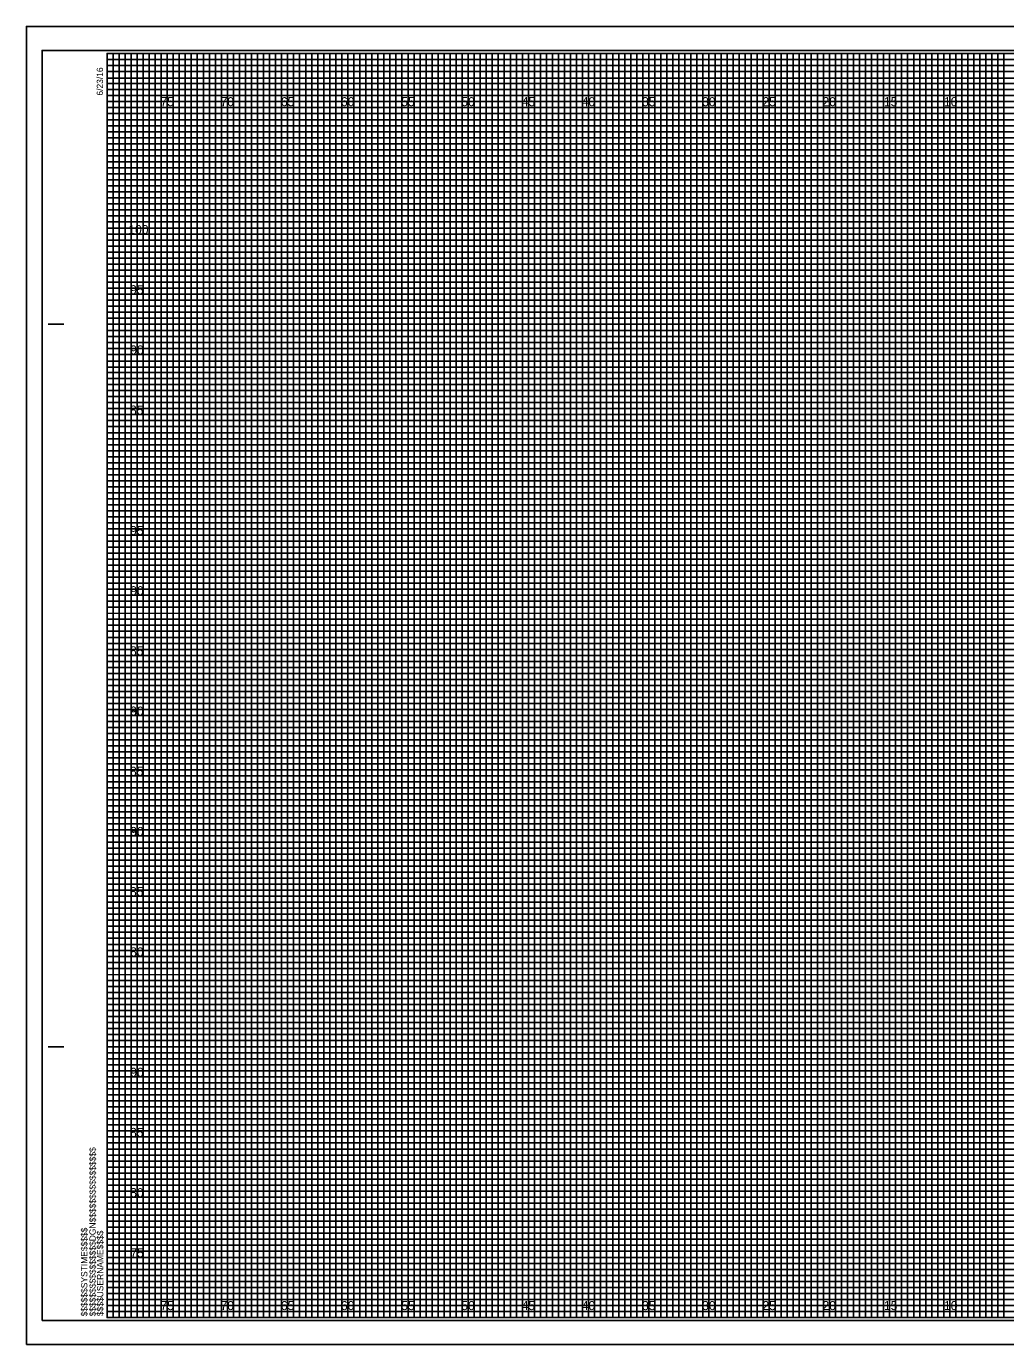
# Model space of a CAD drawing. Extents: x -7 to 182, y -2 to 1647.
# Drawn here: x -6.7 to 74.6, y 217.7 to 327.2 of the extents above; entities that cross this region are included whole.
import ezdxf

# ---------------------------------------------------------------- set-up
doc = ezdxf.new("R2010")
doc.units = 0
for name, color, linetype in [('Exist Cross Section Cell', 7, 'Continuous'), ('Exist XS Ground Line', 7, 'Continuous'), ('Prop CMT Pvmt Course 3', 7, 'Continuous'), ('Prop CMT Pvmt Wedge Surface 1', 7, 'Continuous'), ('Prop CMT Pvmt Wedge Surface 2', 7, 'Continuous'), ('Prop CMT Pvmt Wedge Surface 3', 7, 'Continuous'), ('Prop CMT Shld Paved Course 1', 7, 'Continuous'), ('Prop CMT Shld Paved Course 2', 7, 'Continuous'), ('Prop CMT Shld Paved Course 3', 7, 'Continuous'), ('Prop CMT Slope Grass', 7, 'Continuous'), ('Prop CMT Subgrade Earthwork', 7, 'Continuous')]:
    doc.layers.add(name, color=color, linetype=linetype)

msp = doc.modelspace()

# ---------------------------------------------------------------- linework, layer by layer
at = {"layer": 'Exist XS Ground Line'}
for p, q in [((5, 325), (0, 325)), ((5, 220), (5, 325)), ((15, 325), (10, 325)), ((10, 325), (10, 220)), ((15, 220), (15, 325)), ((25, 325), (20, 325)), ((20, 325), (20, 220)), ((25, 220), (25, 325)), ((35, 325), (30, 325)), ((30, 325), (30, 220)), ((35, 220), (35, 325)), ((45, 325), (40, 325)), ((40, 325), (40, 220)), ((45, 220), (45, 325)), ((55, 325), (50, 325)), ((50, 325), (50, 220)), ((55, 220), (55, 325)), ((65, 325), (60, 325)), ((60, 325), (60, 220)), ((65, 220), (65, 325)), ((75, 325), (70, 325)), ((70, 325), (70, 220)), ((10, 220), (5, 220)), ((20, 220), (15, 220)), ((30, 220), (25, 220)), ((40, 220), (35, 220)), ((50, 220), (45, 220)), ((60, 220), (55, 220)), ((70, 220), (65, 220))]:
    msp.add_line(p, q, dxfattribs=at)
for points in [[(0, 320), (160, 320), (160, 315), (0, 315)], [(0, 310), (160, 310), (160, 305), (0, 305)], [(0, 300), (160, 300), (160, 295), (0, 295)], [(0, 290), (160, 290), (160, 285), (0, 285)], [(0, 280), (160, 280), (160, 275), (0, 275)], [(0, 270), (160, 270), (160, 265), (0, 265)], [(0, 260), (160, 260), (160, 255), (0, 255)], [(0, 250), (160, 250), (160, 245), (0, 245)], [(0, 240), (160, 240), (160, 235), (0, 235)], [(0, 230), (160, 230), (160, 225), (0, 225)]]:
    msp.add_lwpolyline(points, dxfattribs=at)
at = {"layer": 'Prop CMT Pvmt Course 3'}
msp.add_lwpolyline([(-6.7, 217.75), (161.65, 217.75), (161.65, 327.25), (-6.7, 327.25)], close=True, dxfattribs=at)
at = {"layer": 'Prop CMT Pvmt Wedge Surface 1'}
for p, q in [((0, 324.5), (130, 324.5)), ((130, 323.99), (0, 323.99)), ((0, 323.99), (0, 323.5)), ((0, 323.5), (130, 323.5)), ((130, 322.94), (0, 322.94)), ((0, 322.94), (0, 322)), ((0, 322), (160, 322))]:
    msp.add_line(p, q, dxfattribs=at)
for points in [[(0, 321.5), (135, 321.5), (160, 321.5), (160, 321), (0, 321)], [(0, 320.5), (160, 320.5), (160, 319.5), (0, 319.5)], [(0, 319), (160, 319), (160, 318.5), (0, 318.49)], [(0, 318), (160, 318), (160, 317), (0, 317)], [(0, 316.5), (160, 316.5), (160, 316), (0, 316)], [(0, 315.5), (160, 315.5), (160, 314.5), (0, 314.5)], [(0, 314), (160, 314), (160, 313.5), (0, 313.5)], [(0, 313), (160, 313), (160, 312), (0, 312)], [(0, 311.5), (160, 311.5), (160, 311), (0, 311)], [(0, 310.5), (160, 310.5), (160, 309.5), (0, 309.5)], [(0, 309), (160, 309), (160, 308.5), (0, 308.5)], [(0, 308), (160, 308), (160, 306.98), (160, 306.5), (160, 306), (0, 306)], [(0, 307), (160, 307), (160, 306.5), (0, 306.5)], [(0, 305.5), (160, 305.5), (160, 304.5), (0, 304.51)], [(0, 304.51), (160, 304.5), (160, 304), (0, 304)], [(0, 303.5), (160, 303.5), (160, 303), (0, 303)], [(0, 302), (160, 302), (160, 301.5), (0, 301.5)], [(0, 301), (160, 301), (160, 300.5), (0, 300.5)], [(-0.04, 299.44), (160, 299.44), (160, 298.94), (-0.04, 298.94)], [(0, 298.5), (160, 298.5), (160, 298), (0, 298)], [(0, 297), (160, 297), (160, 296.5), (0, 296.5)], [(0, 296), (160, 296), (160, 295.5), (0, 295.5)], [(0, 294.5), (160, 294.5), (160, 294), (0, 294)], [(0, 293.5), (160, 293.5), (160, 293), (0, 293)], [(0, 292), (160, 292), (160, 291.5), (0, 291.5)], [(0, 291), (160, 291), (160, 290.5), (0, 290.5)], [(0, 289.5), (160, 289.5), (160, 288.99), (0, 289)], [(0, 288.5), (160, 288.5), (160, 288), (0, 288)], [(0, 287), (160, 287), (160, 286.5), (0, 286.5)], [(0, 286), (160, 286), (160, 285.5), (0, 285.5)], [(0, 284.5), (160, 284.5), (160, 284), (0, 284)], [(0, 283.5), (160, 283.5), (160, 283), (0, 283)], [(0, 282), (160, 282), (160, 281.5), (0, 281.5)], [(0, 281), (160, 281), (160, 280.5), (0, 280.5)], [(0, 279.5), (160, 279.5), (160, 279), (0, 279)], [(0, 278.5), (160.03, 278.45), (160, 278), (0, 278)], [(0, 277), (160, 277), (160, 276.5), (0, 276.5)], [(0, 276), (160, 276), (160, 275.5), (0, 275.5)], [(0, 274.5), (160, 274.5), (160, 274), (0, 274)], [(0, 273.5), (160, 273.5), (160, 273), (0, 273)], [(0, 272), (160, 272), (160, 271.5), (0, 271.5)], [(0, 271), (160, 271), (160, 270.5), (0, 270.5)], [(0, 269.5), (160, 269.5), (160, 269), (0, 269)], [(0, 268.5), (160, 268.5), (160, 268), (0, 268)], [(0, 267), (160, 267), (160, 266.5), (0, 266.5)], [(0, 266), (160, 266), (160, 265.5), (0, 265.5)], [(0, 264.5), (160, 264.5), (160, 264), (0, 264)], [(0, 263.5), (160, 263.5), (160, 263), (0, 263)], [(0, 262), (160, 262), (160, 261.5), (0, 261.5)], [(0, 261), (160, 261), (160, 260.5), (0, 260.5)], [(0, 259.5), (160, 259.5), (160, 258.99), (0, 259)], [(0, 258.5), (160, 258.5), (160, 258), (0, 258)], [(0, 257), (160, 257), (160, 256.5), (0, 256.5)], [(0, 256), (160, 256), (160, 255.5), (0, 255.5)], [(0, 254.5), (160, 254.5), (160, 254), (0, 254)], [(0, 253.5), (160, 253.5), (160, 253), (0, 253)], [(0, 252), (160, 252), (160, 251.5), (0, 251.5)], [(0, 251), (160, 251), (160, 250.5), (0, 250.5)], [(0, 249.5), (160, 249.5), (160, 249), (0, 249)], [(0, 248.5), (160.03, 248.46), (160, 248), (0, 248)], [(0, 247), (160, 247), (160, 246.5), (0, 246.5)], [(0, 246), (160, 246), (160, 245.5), (0, 245.5)], [(0, 244.5), (160, 244.5), (160, 244), (0, 244)], [(0, 243.5), (160, 243.5), (160, 243), (0, 243)], [(0, 242), (160, 242), (160, 241.5), (0, 241.5)], [(0, 241), (160, 241), (160, 240.5), (0, 240.5)], [(0, 239.5), (160, 239.5), (160, 239), (0, 239)], [(0, 238.5), (160, 238.5), (160, 238), (0, 238)], [(0, 237), (160, 237), (160, 236.5), (0, 236.5)], [(0, 236), (160, 236), (160, 235.5), (0, 235.5)], [(0, 234.5), (160, 234.5), (160, 234), (0, 234)], [(0, 233.5), (160, 233.5), (160, 233), (0, 233)], [(0, 232), (160, 232), (160, 231.5), (0, 231.5)], [(0, 231), (160, 231), (160, 230.5), (0, 230.5)], [(0, 229.5), (160, 229.5), (160, 229), (0, 229)], [(0, 228.5), (160, 228.5), (160, 228), (0, 228)], [(0, 227), (160, 227), (160, 226.5), (0, 226.5)], [(0, 226), (160, 226), (160, 225.5), (0, 225.5)], [(0, 224.5), (160, 224.5), (160, 224), (0, 224)], [(0, 223.5), (160, 223.5), (160, 223), (0, 223)], [(0, 222), (160, 222), (160, 221.5), (0, 221.5)], [(0, 221), (160, 221), (160, 220.5), (0, 220.5)]]:
    msp.add_lwpolyline(points, dxfattribs=at)
at = {"layer": 'Prop CMT Pvmt Wedge Surface 2'}
for p, q in [((-4.9, 302.5), (-3.65, 302.5)), ((-4.85, 302.5), (-3.6, 302.5)), ((-4.9, 242.5), (-3.65, 242.5)), ((-4.85, 242.5), (-3.6, 242.5)), ((0, 220), (0, 220)), ((0, 220), (0, 220)), ((0, 220), (0, 220)), ((0, 220), (0, 220)), ((0, 220), (0, 220)), ((0, 220), (0, 220)), ((0, 220), (0, 220))]:
    msp.add_line(p, q, dxfattribs=at)
msp.add_lwpolyline([(160, 325), (0, 325), (0, 220), (160, 220)], close=True, dxfattribs=at)
at = {"layer": 'Prop CMT Pvmt Wedge Surface 3'}
for points in [[(0, 220), (0.5, 220), (0.5, 325), (1, 325), (1, 220)], [(1, 220), (1.5, 220), (1.5, 325), (2, 325), (2, 220)], [(2.5, 220), (3, 220), (3, 325), (3.5, 325), (3.5, 220)], [(3.5, 220), (4, 220), (4, 325), (4.5, 325), (4.5, 220)], [(5, 220), (5.5, 220), (5.5, 325), (6, 325), (6, 220)], [(6, 220), (6.5, 220), (6.5, 325), (7, 325), (7, 220)], [(7.5, 220), (8, 220), (8, 325), (8.5, 325), (8.5, 220)], [(8.5, 220), (9, 220), (9, 325), (9.5, 325), (9.5, 220)], [(10, 220), (10.5, 220), (10.5, 325), (11, 325), (11, 220)], [(11, 220), (11.5, 220), (11.5, 325), (12, 325), (12, 220)], [(12.5, 220), (13, 220), (13, 325), (13.5, 325), (13.5, 220)], [(13.5, 220), (14, 220), (14, 325), (14.5, 325), (14.5, 220)], [(15, 220), (15.5, 220), (15.5, 325), (16, 325), (16, 220)], [(16, 220), (16.5, 220), (16.5, 325), (17, 325), (17, 220)], [(17.5, 220), (18, 220), (18, 325), (18.5, 325), (18.5, 220)], [(18.5, 220), (19, 220), (19, 325), (19.5, 325), (19.5, 220)], [(20, 220), (20.5, 220), (20.5, 325), (21, 325), (21, 220)], [(21, 220), (21.5, 220), (21.5, 325), (22, 325), (22, 220)], [(22.5, 220), (23, 220), (23, 325), (23.5, 325), (23.5, 220)], [(23.5, 220), (24, 220), (24, 325), (24.5, 325), (24.5, 220)], [(25, 220), (25.5, 220), (25.5, 325), (26, 325), (26, 220)], [(26, 220), (26.5, 220), (26.5, 325), (27, 325), (27, 220)], [(27.5, 220), (28, 220), (28, 325), (28.5, 325), (28.5, 220)], [(28.5, 220), (29, 220), (29, 325), (29.5, 325), (29.5, 220)], [(30, 220), (30.5, 220), (30.5, 325), (31, 325), (31, 220)], [(31, 220), (31.5, 220), (31.5, 325), (32, 325), (32, 220)], [(32.5, 220), (33, 220), (33, 325), (33.5, 325), (33.5, 220)], [(33.5, 220), (34, 220), (34, 325), (34.5, 325), (34.5, 220)], [(35, 220), (35.5, 220), (35.5, 325), (36, 325), (36, 220)], [(36, 220), (36.5, 220), (36.5, 325), (37, 325), (37, 220)], [(37.5, 220), (38, 220), (38, 325), (38.5, 325), (38.5, 220)], [(38.5, 220), (39, 220), (39, 325), (39.5, 325), (39.5, 220)], [(40, 220), (40.5, 220), (40.5, 325), (41, 325), (41, 220)], [(41, 220), (41.5, 220), (41.5, 325), (42, 325), (42, 220)], [(42.5, 220), (43, 220), (43, 325), (43.5, 325), (43.5, 220)], [(43.5, 220), (44, 220), (44, 325), (44.5, 325), (44.5, 220)], [(45, 220), (45.5, 220), (45.5, 325), (46, 325), (46, 220)], [(46, 220), (46.5, 220), (46.5, 325), (47, 325), (47, 220)], [(47.5, 220), (48, 220), (48, 325), (48.5, 325), (48.5, 220)], [(48.5, 220), (49, 220), (49, 325), (49.5, 325), (49.5, 220)], [(50, 220), (50.5, 220), (50.5, 325), (51, 325), (51, 220)], [(51, 220), (51.5, 220), (51.5, 325), (52, 325), (52, 220)], [(52.5, 220), (53, 220), (53, 325), (53.5, 325), (53.5, 220)], [(53.5, 220), (54, 220), (54, 325), (54.5, 325), (54.5, 220)], [(55, 220), (55.5, 220), (55.5, 325), (56, 325), (56, 220)], [(56, 220), (56.5, 220), (56.5, 325), (57, 325), (57, 220)], [(57.5, 220), (58, 220), (58, 325), (58.5, 325), (58.5, 220)], [(58.5, 220), (59, 220), (59, 325), (59.5, 325), (59.5, 220)], [(60, 220), (60.5, 220), (60.5, 325), (61, 325), (61, 220)], [(61, 220), (61.5, 220), (61.5, 325), (62, 325), (62, 220)], [(62.5, 220), (63, 220), (63, 325), (63.5, 325), (63.5, 220)], [(63.5, 220), (64, 220), (64, 325), (64.5, 325), (64.5, 220)], [(65, 220), (65.5, 220), (65.5, 325), (66, 325), (66, 220)], [(66, 220), (66.5, 220), (66.5, 325), (67, 325), (67, 220)], [(67.5, 220), (68, 220), (68, 325), (68.5, 325), (68.5, 220)], [(68.5, 220), (69, 220), (69, 325), (69.5, 325), (69.5, 220)], [(70, 220), (70.5, 220), (70.5, 325), (71, 325), (71, 220)], [(71, 220), (71.5, 220), (71.5, 325), (72, 325), (72, 220)], [(72.5, 220), (73, 220), (73, 325), (73.5, 325), (73.5, 220)], [(73.5, 220), (74, 220), (74, 325), (74.5, 325), (74.5, 220)]]:
    msp.add_lwpolyline(points, dxfattribs=at)
at = {"layer": 'Prop CMT Shld Paved Course 1'}
for p, q in [((5, 220), (5, 325)), ((10, 220), (10, 325)), ((15, 220), (15, 325)), ((20, 220), (20, 325)), ((25, 220), (25, 325)), ((30, 220), (30, 325)), ((35, 220), (35, 325)), ((40, 220), (40, 325)), ((45, 220), (45, 325)), ((50, 220), (50, 325)), ((55, 220), (55, 325)), ((60, 220), (60, 325)), ((65, 220), (65, 325)), ((70, 220), (70, 325)), ((0, 320), (160, 320)), ((0, 315), (160, 315)), ((0, 310), (160, 310)), ((0, 305), (160, 305)), ((0, 300), (160, 300)), ((0, 295), (160, 295)), ((0, 290), (160, 290)), ((0, 285), (160, 285)), ((0, 280), (160, 280)), ((0, 275), (160, 275)), ((0, 270), (160, 270)), ((0, 265), (160, 265)), ((0, 260), (160, 260)), ((0, 255), (160, 255)), ((0, 250), (160, 250)), ((0, 245), (160, 245)), ((0, 240), (160, 240)), ((0, 235), (160, 235)), ((0, 230), (160, 230)), ((0, 225), (160, 225))]:
    msp.add_line(p, q, dxfattribs=at)
at = {"layer": 'Prop CMT Shld Paved Course 2'}
for p, q in [((161.65, 327.25), (-6.7, 327.25)), ((-6.7, 327.25), (-6.7, 217.75)), ((-6.7, 217.75), (161.65, 217.75))]:
    msp.add_line(p, q, dxfattribs=at)
at = {"layer": 'Prop CMT Slope Grass'}
msp.add_lwpolyline([(-5.4, 219.75), (161.2, 219.75), (161.2, 325.25), (-5.4, 325.25)], close=True, dxfattribs=at)
at = {"layer": 'Prop CMT Subgrade Earthwork'}
for points in [[(0, 325), (2.5, 325), (2.5, 220), (7.5, 220), (7.5, 325), (12.5, 325), (12.5, 220), (17.5, 220), (17.5, 325), (22.5, 325), (22.5, 220), (27.5, 220), (27.5, 325), (32.5, 325), (32.5, 220), (37.5, 220), (37.5, 325), (42.5, 325), (42.5, 220), (47.5, 220), (47.5, 325), (52.5, 325), (52.5, 220), (57.5, 220), (57.5, 325), (62.5, 325), (62.5, 220), (67.5, 220), (67.5, 325), (72.5, 325), (72.5, 220), (77.5, 220)], [(0, 322.5), (137.5, 322.5)], [(0, 312.5), (160, 312.5), (160, 317.5), (0, 317.5)], [(0, 302.5), (160, 302.5), (160, 307.5), (0, 307.5)], [(0, 292.5), (160, 292.5), (160, 297.5), (0, 297.5)], [(0, 282.5), (160, 282.5), (160, 287.5), (0, 287.5)], [(0, 272.5), (160, 272.5), (160, 277.5), (0, 277.5)], [(0, 262.5), (160, 262.5), (160, 267.5), (0, 267.5)], [(0, 252.5), (160, 252.5), (160, 257.5), (0, 257.5)], [(0, 242.5), (160, 242.5), (160, 247.5), (0, 247.5)], [(0, 232.5), (160, 232.5), (160, 237.5), (0, 237.5)], [(0, 222.5), (160, 222.5), (160, 227.5), (0, 227.5)]]:
    msp.add_lwpolyline(points, dxfattribs=at)

# ---------------------------------------------------------------- texts
at = {"layer": 'Exist Cross Section Cell'}
for s, p in [('75', (4.44, 320.62)), ('70', (9.43, 320.62)), ('65', (14.44, 320.62)), ('60', (19.43, 320.62)), ('55', (24.44, 320.62)), ('50', (29.43, 320.62)), ('45', (34.44, 320.62)), ('40', (39.43, 320.62)), ('35', (44.44, 320.62)), ('30', (49.43, 320.62)), ('25', (54.44, 320.62)), ('20', (59.43, 320.62)), ('15', (64.53, 320.62)), ('10', (69.52, 320.62)), ('75', (4.44, 220.62)), ('70', (9.43, 220.62)), ('65', (14.44, 220.62)), ('60', (19.43, 220.62)), ('55', (24.44, 220.62)), ('50', (29.43, 220.62)), ('45', (34.44, 220.62)), ('40', (39.43, 220.62)), ('35', (44.44, 220.62)), ('30', (49.43, 220.62)), ('25', (54.44, 220.62)), ('20', (59.43, 220.62)), ('15', (64.53, 220.62)), ('10', (69.52, 220.62))]:
    msp.add_text(s, height=0.75, dxfattribs=at).set_placement(p)
at = {"layer": 'Prop CMT Pvmt Wedge Surface 2'}
for s, p in [('6/23/16', (-0.33, 321.5)), ('$$$$$$$$$$$$$$$$DGN$$$$$$$$$$$$$$$$', (-0.94, 220.09)), ('$$$$$$SYSTIME$$$$$', (-1.63, 220.09)), ('$$$$USERNAME$$$$', (-0.31, 220.12))]:
    msp.add_text(s, height=0.525, rotation=90, dxfattribs=at).set_placement(p)
at = {"layer": 'Prop CMT Shld Paved Course 3'}
for s, p in [('100', (1.77, 310)), ('95', (1.92, 305)), ('90', (1.93, 300)), ('85', (1.91, 295)), ('95', (1.92, 285)), ('90', (1.93, 280)), ('85', (1.91, 275)), ('80', (1.92, 270)), ('90', (1.93, 270)), ('85', (1.91, 265)), ('80', (1.92, 260)), ('90', (1.93, 260)), ('85', (1.91, 255)), ('80', (1.92, 250)), ('90', (1.93, 240)), ('85', (1.91, 235)), ('80', (1.92, 230)), ('75', (1.94, 225))]:
    msp.add_text(s, height=0.75, dxfattribs=at).set_placement(p)

doc.saveas('drawing.dxf')
